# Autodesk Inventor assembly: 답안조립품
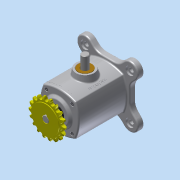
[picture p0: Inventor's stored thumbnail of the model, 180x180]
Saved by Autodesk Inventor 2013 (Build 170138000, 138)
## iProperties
Created: 2016-05
Part Number: 답안조립품
Document SubType Name: Assembly
Designer: Administrator
Author: Administrator
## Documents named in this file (11)
- C:\Users\Administrator\Desktop\460508V1014\답안조립품.iam
- C:\Users\Administrator\Desktop\460508V1014\M4x0.7x12.ipt
- C:\Users\Administrator\Desktop\460508V1014\베어링-6203.ipt
- C:\Users\Administrator\Desktop\460508V1014\본체.ipt
- C:\Users\Administrator\Desktop\460508V1014\부시.ipt
- C:\Users\Administrator\Desktop\460508V1014\스프로킷.ipt
- C:\Users\Administrator\Desktop\460508V1014\슬라이더.ipt
- C:\Users\Administrator\Desktop\460508V1014\오일실.ipt
- C:\Users\Administrator\Desktop\460508V1014\커버.ipt
- C:\Users\Administrator\Desktop\460508V1014\키5x5.ipt
- C:\Users\Administrator\Desktop\460508V1014\편심축.ipt
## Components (8 placed, 1 different names)
1. M4x0.7x12:1
2. M4x0.7x12:3
3. M4x0.7x12:4
4. M4x0.7x12:5
5. M4x0.7x12:2
6. M4x0.7x12:6
7. M4x0.7x12:7
8. M4x0.7x12:8
